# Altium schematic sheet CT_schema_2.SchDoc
size 259 x 238 mm
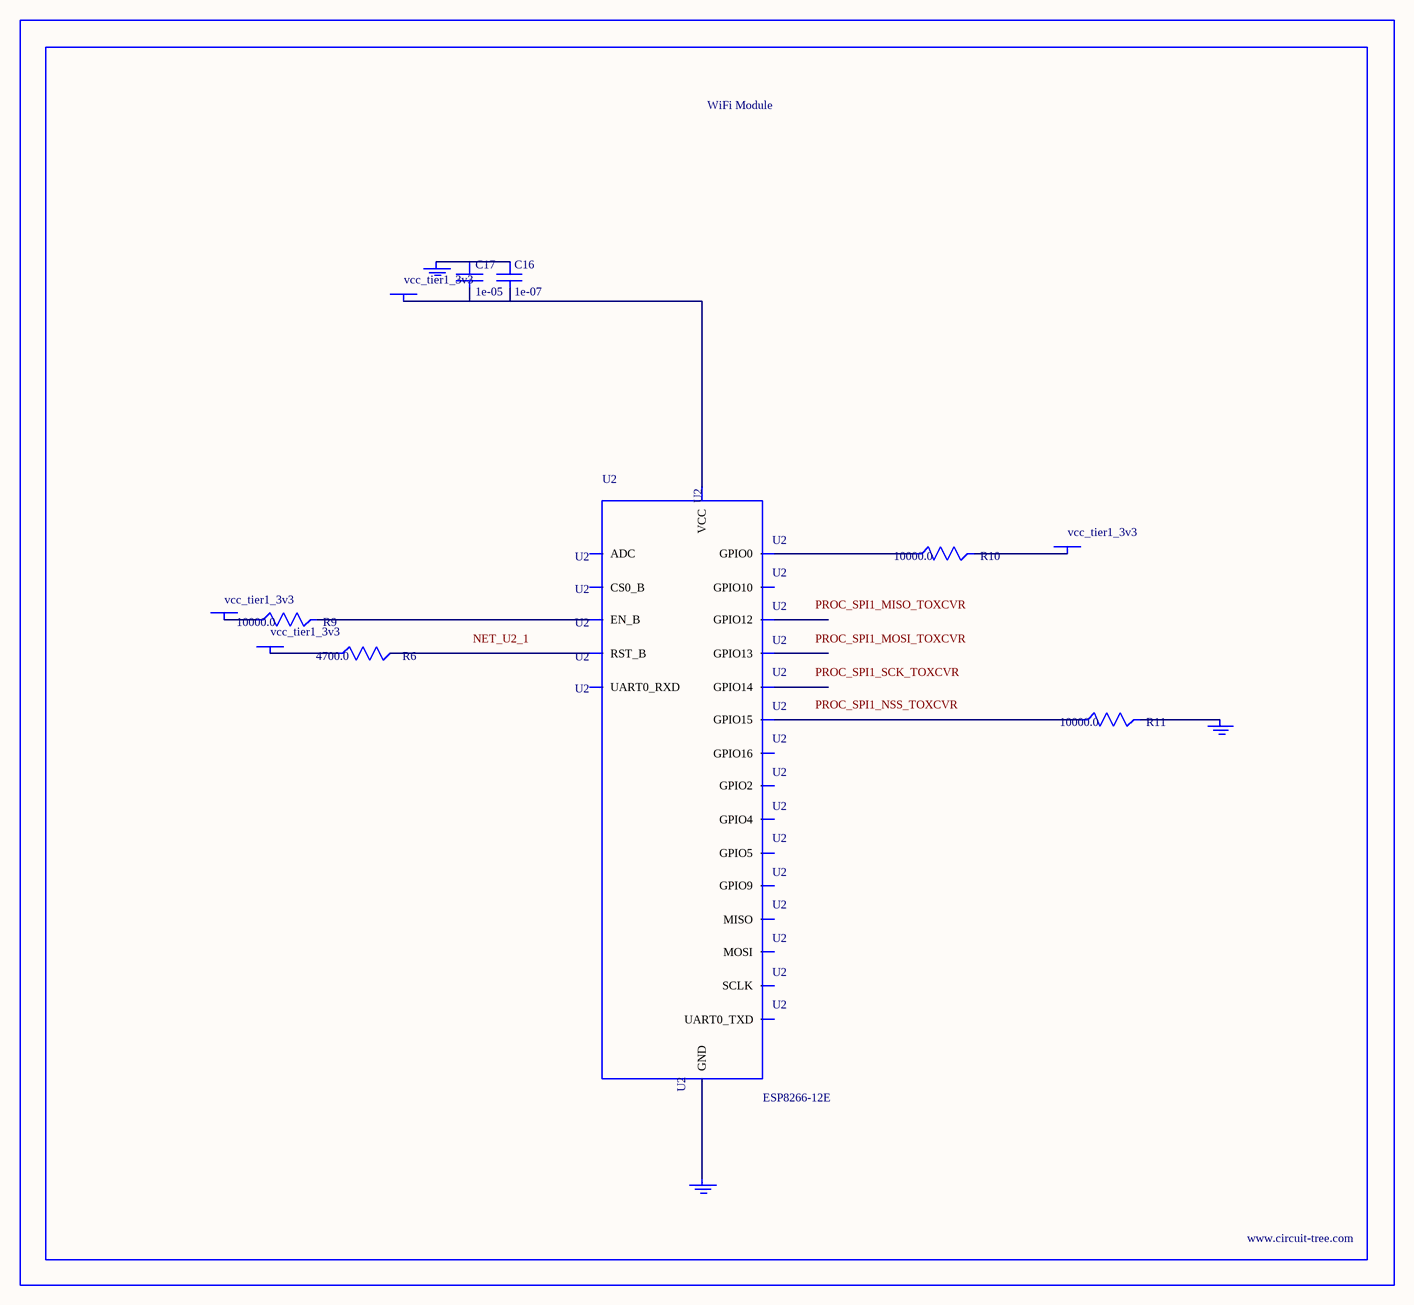
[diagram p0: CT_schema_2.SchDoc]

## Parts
BORDER1  (no value)
C16  1e-07  [C0402]
C17  1e-05  [C0805]
GND_INSTANCE_1_0  (no value)
GND_INSTANCE_1_1  (no value)
GND_INSTANCE_1_2  (no value)
POWER_INSTANCE_1_0  vcc_tier1_3v3
POWER_INSTANCE_1_1  vcc_tier1_3v3
POWER_INSTANCE_1_2  vcc_tier1_3v3
POWER_INSTANCE_1_3  vcc_tier1_3v3
R6  4700.0  [R0603]
R9  10000.0  [R0603]
R10  10000.0  [R0603]
R11  10000.0  [R0603]
U2  ESP8266-12E  [ESP8266-12E]

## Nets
NetC16_1: C16.1 C17.1 GND_INSTANCE_1_0.0(GND)
NetC16_2: C16.2 C17.2 POWER_INSTANCE_1_1.0(PWR) U2.8(VCC)
NetGND_INSTANCE_1_1_0: GND_INSTANCE_1_1.0(GND) R11.2
NetGND_INSTANCE_1_2_0: GND_INSTANCE_1_2.0(GND) U2.15(GND)
NetPOWER_INSTANCE_1_0_0: POWER_INSTANCE_1_0.0(PWR) R9.1
NetPOWER_INSTANCE_1_2_0: POWER_INSTANCE_1_2.0(PWR) R10.2
NetPOWER_INSTANCE_1_3_0: POWER_INSTANCE_1_3.0(PWR) R6.1
NetR6_2: R6.2 U2.1(RST_B)
NetR9_2: R9.2 U2.3(EN_B)
NetR10_1: R10.1 U2.18(GPIO0)
NetR11_1: R11.1 U2.16(GPIO15)

Not connected (* = marked no-connect by the designer): U2 2(ADC) 4(GPIO16) 5(GPIO14) 6(GPIO12) 7(GPIO13) 9(CS0_B) 10(MISO) 11(GPIO9) 12(GPIO10) 13(MOSI) 14(SCLK) 17(GPIO2) 19(GPIO4) 20(GPIO5) 21(UART0_RXD) 22(UART0_TXD)

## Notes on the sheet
- Labels drawn without touching a wire or pin: NET_U2_1, PROC_SPI1_MISO_TOXCVR, PROC_SPI1_MOSI_TOXCVR, PROC_SPI1_NSS_TOXCVR, PROC_SPI1_SCK_TOXCVR

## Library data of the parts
BORDER1 = BORDER_PAGE1
C16 = C0402C104K3RACTU
C17 = C0805C106K8RACTU
GND_INSTANCE_1_0-GND_INSTANCE_1_2 = GND
POWER_INSTANCE_1_0-POWER_INSTANCE_1_3 = PWR
R6 = RC0603JR-074K7L
R9-R11 = RC0603JR-0710KL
